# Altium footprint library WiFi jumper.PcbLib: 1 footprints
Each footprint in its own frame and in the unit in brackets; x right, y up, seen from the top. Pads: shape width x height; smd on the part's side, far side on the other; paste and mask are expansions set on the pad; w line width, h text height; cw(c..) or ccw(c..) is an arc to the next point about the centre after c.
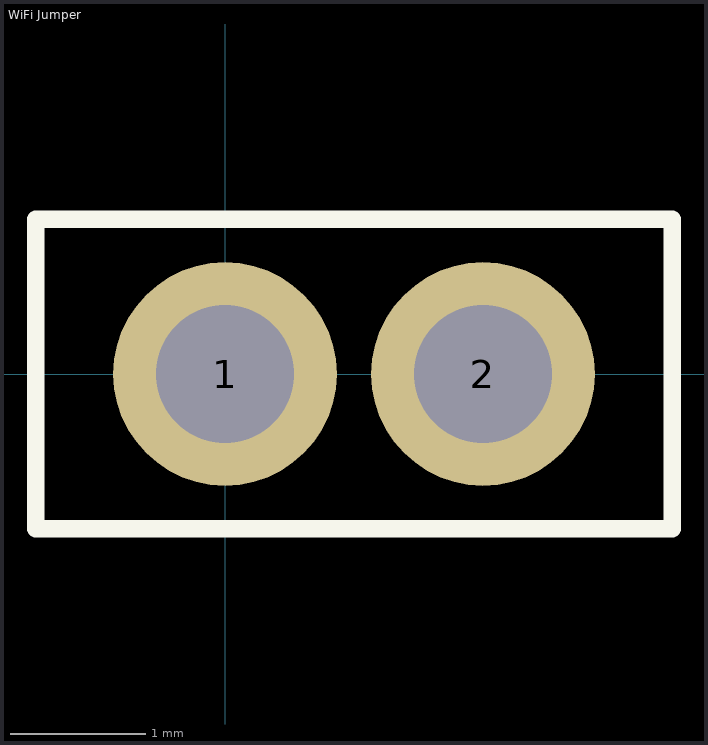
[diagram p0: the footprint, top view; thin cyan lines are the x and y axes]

## WiFi Jumper [mil]
pads (2):
  round 65 hole 40: 1(0,0) 2(75,0)
Top Overlay:
  lines w5: -55,-45 130,-45 130,-22.5 130,22.5 130,45 -55,45 -55,-45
